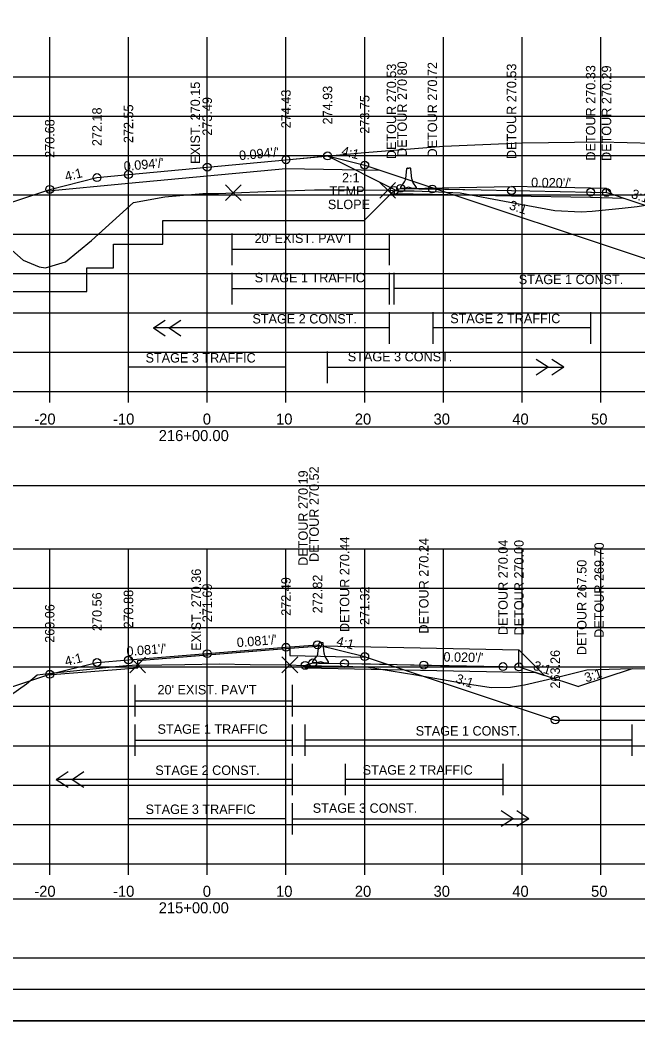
# Model space of a CAD drawing. Extents: x 4667 to 1632277, y -2100 to 724501.
# Drawn here: x 5753.4 to 5831.9, y -1537.1 to -1409.9 of the extents above; entities that cross this region are included whole.
import ezdxf

# ---------------------------------------------------------------- set-up
doc = ezdxf.new("R2010")
doc.units = 0
for name, color, linetype in [('R_Alt Surface', 7, 'Continuous'), ('R_Axis', 7, 'Continuous'), ('R_Axis Annot', 7, 'Continuous'), ('R_Border', 7, 'Continuous'), ('R_Border Notes', 7, 'Continuous'), ('R_Contours', 7, 'Continuous'), ('R_Detour', 7, 'Continuous'), ('R_Detour Annot', 7, 'Continuous'), ('R_Drive', 7, 'Continuous'), ('R_Exist Surface', 7, 'Continuous'), ('R_Fin Surface', 7, 'Continuous'), ('R_Fin Surface Annot', 7, 'Continuous'), ('R_Grid', 7, 'Continuous'), ('R_MOT', 7, 'Continuous'), ('R_No Plot', 7, 'Continuous'), ('R_Point Sym', 7, 'Continuous'), ('R_Proposed CofA', 7, 'Continuous'), ('R_ROW', 7, 'Continuous'), ('R_Temp Easement', 7, 'Continuous'), ('T_Drafting', 7, 'Continuous'), ('T_Notes', 7, 'Continuous')]:
    doc.layers.add(name, color=color, linetype=linetype)

msp = doc.modelspace()

# ---------------------------------------------------------------- linework, layer by layer
at = {"layer": 'R_Alt Surface'}
for points in [[(5756.57, -1431.64), (5767.18, -1430.64), (5777.18, -1429.7), (5787.18, -1428.76), (5799.09, -1429)], [(5756.92, -1493.13), (5768.36, -1492.21), (5768.36, -1491.3), (5777.18, -1490.58), (5787.67, -1489.74), (5787.67, -1490.66), (5797.37, -1490.85)]]:
    msp.add_lwpolyline(points, dxfattribs=at)
at = {"layer": 'R_Axis'}
for p, q in [((5667.18, -1457.11), (5947.18, -1457.11)), ((5757.18, -1458.51), (5757.18, -1457.11)), ((5767.18, -1458.51), (5767.18, -1457.11)), ((5777.18, -1458.51), (5777.18, -1457.11)), ((5787.18, -1458.51), (5787.18, -1457.11)), ((5797.18, -1458.51), (5797.18, -1457.11)), ((5807.18, -1458.51), (5807.18, -1457.11)), ((5817.18, -1458.51), (5817.18, -1457.11)), ((5827.18, -1458.51), (5827.18, -1457.11)), ((5667.18, -1517.11), (5947.18, -1517.11)), ((5757.18, -1518.51), (5757.18, -1517.11)), ((5767.18, -1518.51), (5767.18, -1517.11)), ((5777.18, -1518.51), (5777.18, -1517.11)), ((5787.18, -1518.51), (5787.18, -1517.11)), ((5797.18, -1518.51), (5797.18, -1517.11)), ((5807.18, -1518.51), (5807.18, -1517.11)), ((5817.18, -1518.51), (5817.18, -1517.11)), ((5827.18, -1518.51), (5827.18, -1517.11))]:
    msp.add_line(p, q, dxfattribs=at)
at = {"layer": 'R_Border'}
msp.add_line((5964.36, -1533.11), (5648.18, -1533.11), dxfattribs=at)
at = {"layer": 'R_Detour'}
msp.add_line((5831.16, -1492.33), (5824.32, -1494.61), dxfattribs=at)
for points in [[(5800.9, -1431.95), (5800.92, -1431.58), (5800.9, -1431.95), (5805.76, -1432.05), (5815.82, -1432.25), (5825.86, -1432.44), (5830.02, -1432.53)], [(5800.92, -1431.58), (5800.92, -1431.58), (5800.92, -1431.58), (5801.46, -1431.4), (5801.75, -1431.3), (5804.04, -1431.35), (5805.77, -1431.38), (5811.96, -1431.5), (5815.82, -1431.58), (5818.14, -1431.63), (5825.87, -1431.78), (5825.98, -1431.78), (5827.88, -1431.82), (5828.36, -1431.97), (5831.09, -1432.88), (5837.68, -1435.07)], [(5789.62, -1491.91), (5789.62, -1491.91), (5789.62, -1491.91), (5789.78, -1491.86), (5790.6, -1491.59), (5791.33, -1491.61), (5794.62, -1491.67), (5797.93, -1491.73), (5804.68, -1491.87), (5808.91, -1491.95), (5814.74, -1492.06), (5816.22, -1492.09), (5816.76, -1492.1), (5817.53, -1492.36), (5819.97, -1493.17), (5824.32, -1494.61)]]:
    msp.add_lwpolyline(points, dxfattribs=at)
at = {"layer": 'R_Drive'}
msp.add_lwpolyline([(5787.18, -1427.67), (5797.18, -1426.73), (5807.18, -1425.96), (5817.18, -1425.52), (5827.18, -1425.41), (5837.18, -1425.64), (5847.18, -1426.2), (5849.38, -1426.37), (5857.18, -1426.99), (5865.94, -1427.69), (5867.18, -1427.79), (5877.18, -1428.53), (5887.18, -1429.17), (5897.18, -1429.7)], dxfattribs=at)
at = {"layer": 'R_Exist Surface'}
for points in [[(5746.24, -1433.76), (5753.82, -1440.43), (5755.84, -1441.27), (5756.63, -1441.4), (5757.08, -1441.26), (5759.19, -1440.63), (5762.48, -1437.92), (5767.8, -1433.1), (5771.78, -1432.36), (5773.7, -1432.19), (5776.63, -1431.97), (5777.63, -1431.95), (5778.62, -1431.94), (5780.49, -1431.86), (5784.65, -1431.69), (5790.82, -1431.49), (5795.97, -1431.49), (5800.1, -1431.54), (5801.39, -1431.6), (5803.47, -1431.61), (5806.55, -1431.76), (5809.32, -1431.89), (5815.59, -1433.06), (5821.3, -1434.12), (5824.66, -1434.27), (5826.07, -1434.19), (5829.85, -1433.81), (5831.78, -1433.62), (5838.07, -1432.63)], [(5746.49, -1499.73), (5754.22, -1494.27), (5755.57, -1493.1), (5757.75, -1492.87), (5765.54, -1492.06), (5766.92, -1491.94), (5768.36, -1491.86), (5768.37, -1491.87), (5768.51, -1491.9), (5774.35, -1491.8), (5778.69, -1491.71), (5782.62, -1491.78), (5787.67, -1491.84), (5789.34, -1491.91), (5791.7, -1491.95), (5793.99, -1491.99), (5797.39, -1492.11), (5803.65, -1493.13), (5810.2, -1494.25), (5811.35, -1494.42), (5813.25, -1494.72), (5815.7, -1494.67), (5817.45, -1494.4), (5821.66, -1493.4), (5825.39, -1492.46), (5829.66, -1492.33), (5836.5, -1492.32)]]:
    msp.add_lwpolyline(points, dxfattribs=at)
at = {"layer": 'R_Fin Surface'}
for points in [[(5695.76, -1432.31), (5725.16, -1442.11), (5756.57, -1431.64), (5757.18, -1431.43), (5763.18, -1429.93), (5767.18, -1429.55), (5777.18, -1428.61), (5787.18, -1427.67), (5792.46, -1427.18), (5797.18, -1428.36), (5799.09, -1429), (5802.91, -1430.28), (5834.94, -1440.95), (5838.79, -1440.95), (5869.94, -1440.95), (5872.77, -1439.99), (5895.92, -1432.29)], [(5704.53, -1492.58), (5731.56, -1501.59), (5756.92, -1493.13), (5757.18, -1493.04), (5763.18, -1491.54), (5767.18, -1491.22), (5777.18, -1490.42), (5787.18, -1489.61), (5791.18, -1489.29), (5797.18, -1490.79), (5797.37, -1490.85), (5821.36, -1498.85), (5856.36, -1498.85), (5875.33, -1492.52)]]:
    msp.add_lwpolyline(points, dxfattribs=at)
at = {"layer": 'R_Grid'}
for p, q in [((5757.18, -1457.11), (5757.18, -1412.11)), ((5767.18, -1457.11), (5767.18, -1412.11)), ((5777.18, -1457.11), (5777.18, -1412.11)), ((5787.18, -1457.11), (5787.18, -1412.11)), ((5797.18, -1457.11), (5797.18, -1412.11)), ((5807.18, -1457.11), (5807.18, -1412.11)), ((5817.18, -1457.11), (5817.18, -1412.11)), ((5827.18, -1457.11), (5827.18, -1412.11)), ((5667.18, -1417.11), (5947.18, -1417.11)), ((5667.18, -1422.11), (5947.18, -1422.11)), ((5667.18, -1427.11), (5947.18, -1427.11)), ((5667.18, -1432.11), (5947.18, -1432.11)), ((5667.18, -1437.11), (5947.18, -1437.11)), ((5667.18, -1442.11), (5947.18, -1442.11)), ((5667.18, -1447.11), (5947.18, -1447.11)), ((5667.18, -1452.11), (5947.18, -1452.11)), ((5667.18, -1457.11), (5947.18, -1457.11)), ((5667.18, -1477.11), (5947.18, -1477.11)), ((5757.18, -1517.11), (5757.18, -1477.11)), ((5767.18, -1517.11), (5767.18, -1477.11)), ((5777.18, -1517.11), (5777.18, -1477.11)), ((5787.18, -1517.11), (5787.18, -1477.11)), ((5797.18, -1517.11), (5797.18, -1477.11)), ((5807.18, -1517.11), (5807.18, -1477.11)), ((5817.18, -1517.11), (5817.18, -1477.11)), ((5827.18, -1517.11), (5827.18, -1477.11)), ((5667.18, -1482.11), (5947.18, -1482.11)), ((5667.18, -1487.11), (5947.18, -1487.11)), ((5667.18, -1492.11), (5947.18, -1492.11)), ((5667.18, -1497.11), (5947.18, -1497.11)), ((5667.18, -1502.11), (5947.18, -1502.11)), ((5667.18, -1507.11), (5947.18, -1507.11)), ((5667.18, -1512.11), (5947.18, -1512.11)), ((5667.18, -1517.11), (5947.18, -1517.11))]:
    msp.add_line(p, q, dxfattribs=at)
at = {"layer": 'R_MOT'}
for p, q in [((5802.38, -1430.1), (5802.54, -1428.79)), ((5802.61, -1428.74), (5802.8, -1428.74)), ((5802.99, -1428.74), (5802.8, -1428.74)), ((5803.17, -1430.12), (5803.05, -1428.8)), ((5801.75, -1431.14), (5802.22, -1430.49)), ((5803.75, -1431.18), (5803.31, -1430.51)), ((5801.75, -1431.3), (5801.75, -1431.14)), ((5802.25, -1431.31), (5801.75, -1431.3)), ((5802.75, -1431.16), (5802.25, -1431.31)), ((5803.25, -1431.33), (5802.75, -1431.16)), ((5803.75, -1431.34), (5803.25, -1431.33)), ((5803.75, -1431.34), (5803.75, -1431.18)), ((5791.23, -1490.39), (5791.39, -1489.08)), ((5791.46, -1489.02), (5791.65, -1489.03)), ((5791.84, -1489.03), (5791.65, -1489.03)), ((5792.02, -1490.4), (5791.9, -1489.09)), ((5790.6, -1491.42), (5791.07, -1490.78)), ((5790.6, -1491.59), (5790.6, -1491.42)), ((5791.1, -1491.6), (5790.6, -1491.59)), ((5791.6, -1491.44), (5791.1, -1491.6)), ((5792.1, -1491.62), (5791.6, -1491.44)), ((5792.6, -1491.63), (5792.1, -1491.62)), ((5792.6, -1491.46), (5792.15, -1490.8)), ((5792.6, -1491.63), (5792.6, -1491.46))]:
    msp.add_line(p, q, dxfattribs=at)
for centre, radius, start, end in [((5802.6, -1428.8), 0.0625, 88.8765, 172.8675), ((5802.99, -1428.81), 0.0625, 4.8855, 88.8765), ((5801.55, -1430), 0.833, 323.8845, 352.8675), ((5804, -1430.05), 0.833, 184.8855, 213.8685), ((5791.45, -1489.09), 0.0625, 88.8786, 172.8696), ((5791.84, -1489.09), 0.0625, 4.8876, 88.8786), ((5790.4, -1490.29), 0.833, 323.8866, 352.8696), ((5792.85, -1490.33), 0.833, 184.8876, 213.8706)]:
    msp.add_arc(centre, radius, start, end, dxfattribs=at)
at = {"layer": 'R_No Plot'}
msp.add_line((5635.78, -1537.09), (5969.12, -1537.09), dxfattribs=at)
for points in [[(5635.78, -1323.75), (5969.12, -1323.75), (5969.12, -1537.09), (5635.78, -1537.09)], [(5882.1, -1327.65), (5901.72, -1327.65), (5901.72, -1337.53), (5917.84, -1337.53), (5941.04, -1337.53), (5941.04, -1361.86), (5964.36, -1361.86), (5964.36, -1533.11), (5648.18, -1533.11), (5648.18, -1327.65)]]:
    msp.add_lwpolyline(points, close=True, dxfattribs=at)
for points in [[(5800.1, -1431.54), (5799.1, -1430.54), (5800.1, -1431.54), (5799.1, -1432.54), (5800.1, -1431.54), (5801.1, -1432.54), (5800.1, -1431.54), (5801.1, -1430.54)], [(5780.49, -1431.86), (5779.49, -1430.86), (5780.49, -1431.86), (5779.49, -1432.86), (5780.49, -1431.86), (5781.49, -1432.86), (5780.49, -1431.86), (5781.49, -1430.86)], [(5768.36, -1491.86), (5767.36, -1490.86), (5768.36, -1491.86), (5767.36, -1492.86), (5768.36, -1491.86), (5769.36, -1492.86), (5768.36, -1491.86), (5769.36, -1490.86)], [(5787.67, -1491.84), (5786.67, -1490.84), (5787.67, -1491.84), (5786.67, -1492.84), (5787.67, -1491.84), (5788.67, -1492.84), (5787.67, -1491.84), (5788.67, -1490.84)]]:
    msp.add_lwpolyline(points, dxfattribs=at)
for centre in [(5792.46, -1427.18), (5777.18, -1428.61), (5787.18, -1427.67), (5797.18, -1428.36), (5763.18, -1429.93), (5767.18, -1429.55), (5757.18, -1431.43), (5800.92, -1431.58), (5801.75, -1431.3), (5805.77, -1431.38), (5815.82, -1431.58), (5825.87, -1431.78), (5827.88, -1431.82), (5787.18, -1489.61), (5791.18, -1489.29), (5777.18, -1490.42), (5797.18, -1490.79), (5763.18, -1491.54), (5767.18, -1491.22), (5789.62, -1491.91), (5790.6, -1491.59), (5794.62, -1491.67), (5804.68, -1491.87), (5814.74, -1492.06), (5816.76, -1492.1), (5757.18, -1493.04), (5821.36, -1498.85)]:
    msp.add_circle(centre, 0.5, dxfattribs=at)
at = {"layer": 'R_Point Sym'}
for p, q in [((5789.62, -1491.91), (5789.62, -1492.23)), ((5789.62, -1492.23), (5818.92, -1492.82))]:
    msp.add_line(p, q, dxfattribs=at)
at = {"layer": 'R_Proposed CofA'}
for p, q in [((5770.34, -1449.04), (5771.84, -1448.04)), ((5772.34, -1449.04), (5773.84, -1448.04)), ((5770.34, -1449.04), (5771.84, -1450.04)), ((5772.34, -1449.04), (5773.84, -1450.04)), ((5820.46, -1454.04), (5818.96, -1453.04)), ((5822.46, -1454.04), (5820.96, -1453.04)), ((5820.46, -1454.04), (5818.96, -1455.04)), ((5822.46, -1454.04), (5820.96, -1455.04)), ((5758.01, -1506.4), (5759.51, -1505.4)), ((5760.01, -1506.4), (5761.51, -1505.4)), ((5758.01, -1506.4), (5759.51, -1507.4)), ((5760.01, -1506.4), (5761.51, -1507.4)), ((5816.01, -1511.4), (5814.51, -1510.4)), ((5818.01, -1511.4), (5816.51, -1510.4)), ((5816.01, -1511.4), (5814.51, -1512.4)), ((5818.01, -1511.4), (5816.51, -1512.4))]:
    msp.add_line(p, q, dxfattribs=at)
for points in [[(5667.23, -1469.05), (5947.13, -1469.05), (5947.13, -1461.63), (5667.23, -1461.63)], [(5667.23, -1529.05), (5947.13, -1529.05), (5947.13, -1521.63), (5667.23, -1521.63)]]:
    msp.add_lwpolyline(points, close=True, dxfattribs=at)
at = {"layer": 'R_ROW'}
for p, q in [((5800.92, -1431.58), (5797.09, -1435.4)), ((5771.54, -1435.4), (5797.09, -1435.4)), ((5771.54, -1438.4), (5771.54, -1435.4)), ((5765.26, -1438.4), (5771.54, -1438.4)), ((5765.26, -1441.4), (5765.26, -1438.4)), ((5761.89, -1444.4), (5761.89, -1441.4)), ((5761.89, -1441.4), (5765.26, -1441.4)), ((5751.52, -1444.4), (5761.89, -1444.4))]:
    msp.add_line(p, q, dxfattribs=at)
at = {"layer": 'R_Temp Easement'}
for p, q in [((5780.34, -1441.04), (5780.34, -1437.04)), ((5800.34, -1441.04), (5800.34, -1437.04)), ((5780.34, -1439.04), (5800.34, -1439.04)), ((5780.34, -1446.04), (5780.34, -1442.04)), ((5800.34, -1446.04), (5800.34, -1442.04)), ((5800.9, -1446.04), (5800.9, -1442.04)), ((5780.34, -1444.04), (5800.34, -1444.04)), ((5846.04, -1444.04), (5800.9, -1444.04)), ((5800.34, -1451.04), (5800.34, -1447.04)), ((5805.88, -1451.04), (5805.88, -1447.04)), ((5825.88, -1451.04), (5825.88, -1447.04)), ((5800.34, -1449.04), (5770.34, -1449.04)), ((5825.88, -1449.04), (5805.88, -1449.04)), ((5767.18, -1456.04), (5767.18, -1452.04)), ((5787.18, -1456.04), (5787.18, -1452.04)), ((5792.46, -1456.04), (5792.46, -1452.04)), ((5787.18, -1454.04), (5767.18, -1454.04)), ((5792.46, -1454.04), (5822.46, -1454.04)), ((5768.01, -1498.4), (5768.01, -1494.4)), ((5788.01, -1498.4), (5788.01, -1494.4)), ((5768.01, -1496.4), (5788.01, -1496.4)), ((5768.01, -1503.4), (5768.01, -1499.4)), ((5788.01, -1503.4), (5788.01, -1499.4)), ((5789.62, -1503.4), (5789.62, -1499.4)), ((5831.16, -1503.4), (5831.16, -1499.4)), ((5768.01, -1501.4), (5788.01, -1501.4)), ((5831.16, -1501.4), (5789.62, -1501.4)), ((5788.01, -1508.4), (5788.01, -1504.4)), ((5794.76, -1508.4), (5794.76, -1504.4)), ((5814.76, -1508.4), (5814.76, -1504.4)), ((5788.01, -1506.4), (5758.01, -1506.4)), ((5814.76, -1506.4), (5794.76, -1506.4)), ((5767.18, -1513.4), (5767.18, -1509.4)), ((5787.18, -1513.4), (5787.18, -1509.4)), ((5788.01, -1513.4), (5788.01, -1509.4)), ((5787.18, -1511.4), (5767.18, -1511.4)), ((5788.01, -1511.4), (5818.01, -1511.4))]:
    msp.add_line(p, q, dxfattribs=at)
at = {"layer": 'T_Drafting'}
msp.add_line((5792.46, -1427.18), (5801.12, -1431.51), dxfattribs=at)
at = {"layer": 'T_Notes'}
for p, q in [((5827.88, -1431.3), (5815.82, -1431.06)), ((5827.88, -1431.82), (5827.88, -1431.3)), ((5827.88, -1431.3), (5828.66, -1432.07)), ((5791.69, -1489.42), (5816.76, -1489.92)), ((5816.76, -1492.1), (5816.76, -1489.92)), ((5816.76, -1489.92), (5820.02, -1493.18))]:
    msp.add_line(p, q, dxfattribs=at)
for points in [[(5802.63, -1431.32), (5815.82, -1431.06)], [(5802.63, -1431.32), (5811.96, -1431.5), (5815.82, -1431.58), (5818.14, -1431.63), (5825.87, -1431.78), (5827.88, -1431.82), (5828.36, -1431.97), (5828.66, -1432.07)], [(5768.36, -1491.86), (5768.36, -1491.3), (5787.67, -1489.74), (5791.69, -1489.42)], [(5768.36, -1491.86), (5768.37, -1491.87), (5768.51, -1491.9), (5774.35, -1491.8), (5778.69, -1491.71), (5782.62, -1491.78), (5787.67, -1491.84), (5789.34, -1491.91), (5789.62, -1491.91), (5790.6, -1491.59), (5794.62, -1491.67), (5816.76, -1492.1), (5820.02, -1493.18)]]:
    msp.add_lwpolyline(points, dxfattribs=at)

# ---------------------------------------------------------------- texts
at = {"layer": 'R_Axis Annot'}
for s, p in [('-20', (5755.22, -1461.31)), ('-10', (5765.22, -1461.31)), ('0', (5776.62, -1461.31)), ('10', (5785.92, -1461.31)), ('20', (5795.92, -1461.31)), ('30', (5805.92, -1461.31)), ('40', (5815.92, -1461.31)), ('50', (5825.92, -1461.31)), ('216+00.00', (5771.02, -1463.41)), ('-20', (5755.22, -1521.31)), ('-10', (5765.22, -1521.31)), ('0', (5776.62, -1521.31)), ('10', (5785.92, -1521.31)), ('20', (5795.92, -1521.31)), ('30', (5805.92, -1521.31)), ('40', (5815.92, -1521.31)), ('50', (5825.92, -1521.31)), ('215+00.00', (5771.02, -1523.41))]:
    msp.add_text(s, height=1.4, dxfattribs=at).set_placement(p)
at = {"layer": 'R_Border Notes'}
for s, p in [('2:1', (5794.3, -1430.54)), ('TEMP.', (5792.7, -1432.24)), ('SLOPE', (5792.5, -1433.94))]:
    msp.add_text(s, height=1.2, dxfattribs=at).set_placement(p)
at = {"layer": 'R_Contours'}
msp.add_text('3:1', height=1.2, rotation=18.7248, dxfattribs=at).set_placement((5825.31, -1494.09))
at = {"layer": 'R_Detour Annot'}
for s, rotation, p in [("0.020'/'", 358.875, (5818.3, -1431.13)), ('3:1', 341.6514, (5830.93, -1432.49)), ("0.020'/'", 358.8778, (5807.17, -1491.42)), ('3:1', 341.6769, (5818.48, -1492.42))]:
    msp.add_text(s, height=1.2, rotation=rotation, dxfattribs=at).set_placement(p)
at = {"layer": 'R_Fin Surface Annot'}
for s, rotation, p in [('DETOUR 270.80', 90, (5802.53, -1427.3)), ('DETOUR 270.72', 90, (5806.37, -1427.38)), ('DETOUR 270.53', 90, (5801.17, -1427.59)), ('DETOUR 270.53', 90, (5816.42, -1427.58)), ('DETOUR 270.33', 90, (5826.47, -1427.78)), ('DETOUR 270.29', 90, (5828.48, -1427.82)), ('274.43', 90, (5787.78, -1423.67)), ('274.93', 90, (5793.06, -1423.18)), ('273.49', 90, (5777.78, -1424.61)), ('273.75', 90, (5797.78, -1424.36)), ('272.18', 90, (5763.78, -1425.93)), ('272.55', 90, (5767.78, -1425.55)), ('270.68', 90, (5757.78, -1427.43)), ("0.094'/'", 5.37, (5781.28, -1427.73)), ('4:1', 345.9638, (5794.14, -1427.08)), ("0.094'/'", 5.37, (5766.64, -1429.1)), ('4:1', 14.0362, (5759.26, -1430.4)), ('3:1', 341.5651, (5815.43, -1433.92)), ('DETOUR 270.19', 90, (5789.95, -1479.26)), ('DETOUR 270.52', 90, (5791.35, -1478.76)), ('DETOUR 270.44', 90, (5795.22, -1487.67)), ('DETOUR 270.24', 90, (5805.28, -1487.87)), ('DETOUR 270.04', 90, (5815.34, -1488.06)), ('DETOUR 270.00', 90, (5817.36, -1488.1)), ('DETOUR 269.70', 90, (5827.54, -1488.41)), ('DETOUR 267.50', 90, (5825.34, -1490.61)), ('271.69', 90, (5777.78, -1486.42)), ('272.49', 90, (5787.78, -1485.61)), ('272.82', 90, (5791.78, -1485.29)), ('270.56', 90, (5763.78, -1487.54)), ('270.88', 90, (5767.78, -1487.22)), ('271.32', 90, (5797.78, -1486.79)), ('269.06', 90, (5757.78, -1489.04)), ("0.081'/'", 4.6025, (5766.98, -1490.74)), ("0.081'/'", 4.6025, (5780.98, -1489.61)), ('4:1', 345.9638, (5793.5, -1489.35)), ('4:1', 14.0362, (5759.26, -1492.01)), ('263.26', 90, (5821.96, -1494.85)), ('3:1', 341.5651, (5808.64, -1494.08))]:
    msp.add_text(s, height=1.2, rotation=rotation, dxfattribs=at).set_placement(p)
at = {"layer": 'R_Temp Easement'}
for s, p in [('EXIST. 270.15', (5776.26, -1428.19)), ('EXIST. 270.36', (5776.38, -1490.06))]:
    msp.add_text(s, height=1.2, rotation=90, dxfattribs=at).set_placement(p)
for s, height, p in [("20' EXIST. PAV'T", 1.2, (5783.2, -1438.24)), ('STAGE 1 TRAFFIC', 1.2, (5783.2, -1443.24)), ('STAGE 1 CONST.', 1.1985, (5816.74, -1443.47)), ('STAGE 2 CONST.', 1.1985, (5782.92, -1448.47)), ('STAGE 2 TRAFFIC', 1.1985, (5808.04, -1448.43)), ('STAGE 3 TRAFFIC', 1.1985, (5769.35, -1453.43)), ('STAGE 3 CONST.', 1.1985, (5795.03, -1453.28)), ("20' EXIST. PAV'T", 1.2, (5770.87, -1495.6)), ('STAGE 1 TRAFFIC', 1.2, (5770.87, -1500.6)), ('STAGE 1 CONST.', 1.1985, (5803.65, -1500.83)), ('STAGE 2 CONST.', 1.1985, (5770.59, -1505.83)), ('STAGE 2 TRAFFIC', 1.1985, (5796.92, -1505.79)), ('STAGE 3 TRAFFIC', 1.1985, (5769.35, -1510.79)), ('STAGE 3 CONST.', 1.1985, (5790.58, -1510.64))]:
    msp.add_text(s, height=height, dxfattribs=at).set_placement(p)

doc.saveas('drawing.dxf')
